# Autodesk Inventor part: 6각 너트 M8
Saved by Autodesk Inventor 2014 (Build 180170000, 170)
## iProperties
Created: 2026-09
Part Number: 6각 너트 M8
Material: 일반
Document SubType Name: Modeling
Designer: dg
Density: 1 g/cm^3
Appearance: 기본값
Author: dg
Author: jhkim
Description: 6각 너트
Creation Date: 2026-08-27
Sending System: Autodesk Inventor 2027
Preprocessor: ST-DEVELOPER v20.1
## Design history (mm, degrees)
node "6각 너트 M81"
body "Solid1"
node "기준1"
